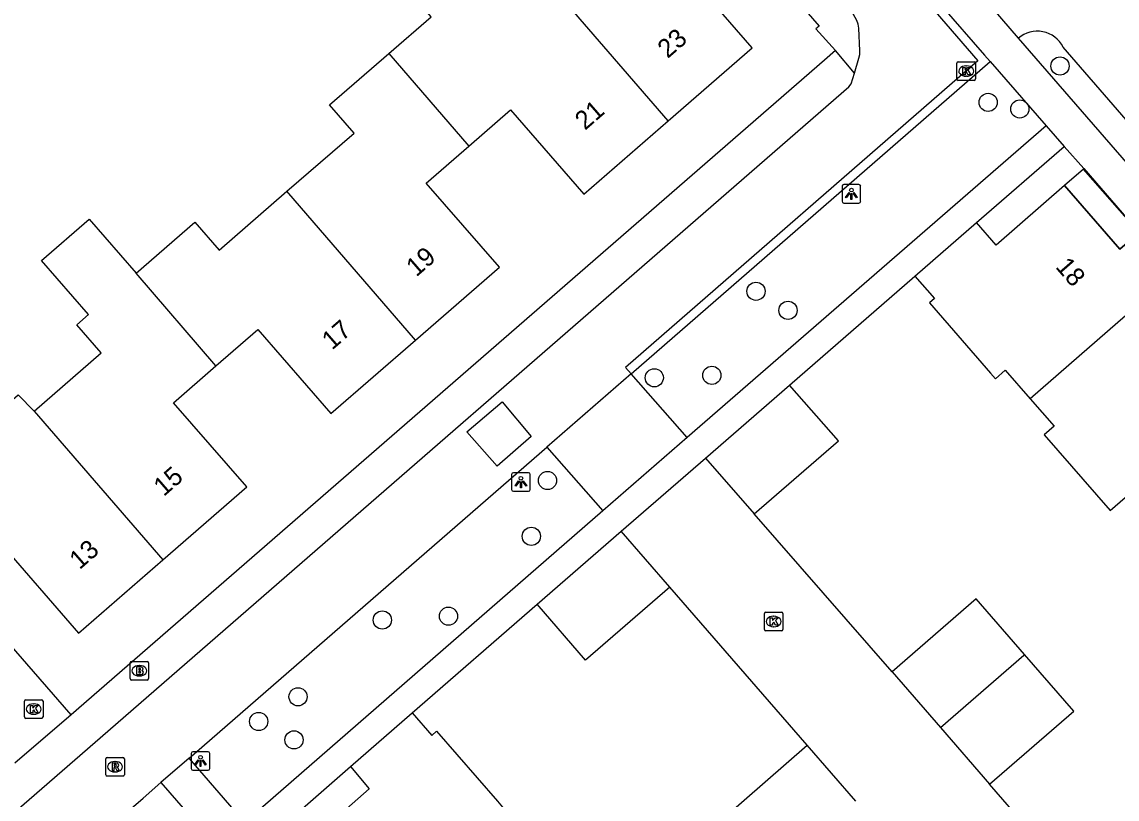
# Model space of a CAD drawing. Extents: x 155888 to 156864, y 383882 to 384671.
# Drawn here: x 156279.9 to 156338.8, y 384195.3 to 384237.1 of the extents above; entities that cross this region are included whole.
import ezdxf

# ---------------------------------------------------------------- set-up
doc = ezdxf.new("R2010")
doc.units = 0
for name, color, linetype in [('IMGEO_Boom', 7, 'Continuous'), ('IMGEO_Brandkraan', 7, 'Continuous'), ('IMGEO_Fietspad_gesloten', 7, 'Continuous'), ('IMGEO_Kolk', 7, 'Continuous'), ('IMGEO_Lichtpunt', 7, 'Continuous'), ('IMGEO_Muur', 7, 'Continuous'), ('IMGEO_Pand', 7, 'Continuous'), ('IMGEO_Pand_nummerreeks', 7, 'Continuous'), ('IMGEO_Pand_overbouw', 7, 'Continuous'), ('IMGEO_Rijbaan_lokaal_gesloten', 7, 'Continuous'), ('IMGEO_Rijbaan_lokaal_open', 7, 'Continuous'), ('IMGEO_Rioolput', 7, 'Continuous'), ('IMGEO_Voetpad_open', 7, 'Continuous')]:
    doc.layers.add(name, color=color, linetype=linetype)

msp = doc.modelspace()

# ---------------------------------------------------------------- linework, layer by layer
at = {"layer": 'IMGEO_Boom'}
for centre in [(156335.691, 384234.728), (156331.826, 384232.771), (156333.53, 384232.42), (156319.34, 384222.609), (156321.063, 384221.583), (156313.87, 384217.956), (156316.967, 384218.087), (156308.129, 384212.429), (156307.261, 384209.427), (156299.244, 384204.922), (156302.801, 384205.128), (156294.714, 384200.793), (156292.594, 384199.464), (156294.493, 384198.473)]:
    msp.add_circle(centre, 0.489, dxfattribs=at)
at = {"layer": 'IMGEO_Brandkraan'}
for p, q in [((156285.677, 384201.769), (156285.677, 384202.621)), ((156285.752, 384202.695), (156286.604, 384202.695)), ((156286.165, 384202.475), (156286.19, 384202.475)), ((156286.678, 384202.621), (156286.678, 384201.769)), ((156286.188, 384201.915), (156286.163, 384201.915)), ((156286.604, 384201.695), (156285.752, 384201.695))]:
    msp.add_line(p, q, dxfattribs=at)
for points in [[(156285.677, 384201.769), (156285.677, 384202.621)], [(156285.752, 384202.695), (156286.604, 384202.695)], [(156286.025, 384202.395), (156286.025, 384201.995), (156286.238, 384201.995)], [(156286.256, 384202.395), (156286.025, 384202.395)], [(156286.678, 384202.621), (156286.678, 384201.769)], [(156286.204, 384202.314), (156286.15, 384202.314), (156286.15, 384202.238)], [(156286.15, 384202.238), (156286.203, 384202.238)], [(156286.212, 384202.162), (156286.15, 384202.162), (156286.15, 384202.081)], [(156286.15, 384202.081), (156286.212, 384202.081)], [(156286.604, 384201.695), (156285.752, 384201.695)]]:
    msp.add_lwpolyline(points, dxfattribs=at)
for centre, radius, start, end in [((156285.754, 384202.619), 0.0765, 91.55205, 178.44795), ((156285.754, 384202.619), 0.0765, 91.55205, 178.44795), ((156286.26, 384202.25), 0.145, 59.4692, 91.53667), ((156286.602, 384202.619), 0.0765, 1.55205, 88.44795), ((156286.602, 384202.619), 0.0765, 1.55205, 88.44795), ((156286.205, 384202.276), 0.0379, 267.82845, 90.93552), ((156286.213, 384202.121), 0.0404, 269.87594, 90.50774), ((156286.244, 384202.246), 0.251, 268.66757, 293.53466), ((156286.285, 384202.297), 0.0922, 285.51372, 58.15012), ((156286.29, 384202.105), 0.105, 301.31148, 78.98903), ((156285.754, 384201.771), 0.0765, 181.55205, 268.44795), ((156285.754, 384201.771), 0.0765, 181.55205, 268.44795), ((156286.602, 384201.771), 0.0765, 271.55205, 358.44795), ((156286.602, 384201.771), 0.0765, 271.55205, 358.44795)]:
    msp.add_arc(centre, radius, start, end, dxfattribs=at)
for centre, major_axis, ratio, start_param, end_param in [((156286.164, 384202.195), (-0.387, 0.002), 0.722429, 4.712389, 7.853982), ((156286.189, 384202.195), (-0.39, 0.002), 0.717154, 1.570796, 4.712389)]:
    msp.add_ellipse(centre, major_axis=major_axis, ratio=ratio, start_param=start_param, end_param=end_param, dxfattribs=at)
at = {"layer": 'IMGEO_Fietspad_gesloten'}
for points in [[(156333.453, 384236.224), (156330.765, 384239.365)], [(156363.796, 384203.508), (156359.945, 384207.962), (156335.855, 384235.751)]]:
    msp.add_lwpolyline(points, dxfattribs=at)
msp.add_arc((156334.468, 384235.043), 1.557, 27.03332, 130.68647, dxfattribs=at)
at = {"layer": 'IMGEO_Kolk'}
for p, q in [((156330.146, 384234.032), (156330.146, 384234.884)), ((156330.221, 384234.958), (156331.073, 384234.958)), ((156331.147, 384234.884), (156331.147, 384234.032)), ((156330.634, 384234.738), (156330.659, 384234.738)), ((156331.073, 384233.958), (156330.221, 384233.958)), ((156330.657, 384234.178), (156330.632, 384234.178)), ((156319.865, 384205.343), (156320.717, 384205.343)), ((156319.79, 384204.417), (156319.79, 384205.269)), ((156320.278, 384205.123), (156320.303, 384205.123)), ((156320.791, 384205.269), (156320.791, 384204.417)), ((156320.717, 384204.343), (156319.865, 384204.343)), ((156320.301, 384204.563), (156320.276, 384204.563)), ((156280.074, 384200.631), (156280.926, 384200.631)), ((156279.999, 384199.705), (156279.999, 384200.557)), ((156280.487, 384200.411), (156280.512, 384200.411)), ((156281, 384200.557), (156281, 384199.705)), ((156280.926, 384199.631), (156280.074, 384199.631)), ((156280.51, 384199.851), (156280.485, 384199.851))]:
    msp.add_line(p, q, dxfattribs=at)
for points in [[(156330.146, 384234.032), (156330.146, 384234.884)], [(156330.221, 384234.958), (156331.073, 384234.958)], [(156331.147, 384234.884), (156331.147, 384234.032)], [(156330.467, 384234.658), (156330.59, 384234.658), (156330.59, 384234.507), (156330.72, 384234.658), (156330.884, 384234.658), (156330.738, 384234.507), (156330.891, 384234.258), (156330.739, 384234.258), (156330.654, 384234.422), (156330.59, 384234.355), (156330.59, 384234.258), (156330.467, 384234.258), (156330.467, 384234.658)], [(156331.073, 384233.958), (156330.221, 384233.958)], [(156319.865, 384205.343), (156320.717, 384205.343)], [(156319.79, 384204.417), (156319.79, 384205.269)], [(156320.111, 384205.043), (156320.234, 384205.043), (156320.234, 384204.892), (156320.364, 384205.043), (156320.528, 384205.043), (156320.382, 384204.892), (156320.535, 384204.643), (156320.383, 384204.643), (156320.298, 384204.807), (156320.234, 384204.74), (156320.234, 384204.643), (156320.111, 384204.643), (156320.111, 384205.043)], [(156320.791, 384205.269), (156320.791, 384204.417)], [(156320.717, 384204.343), (156319.865, 384204.343)], [(156280.074, 384200.631), (156280.926, 384200.631)], [(156279.999, 384199.705), (156279.999, 384200.557)], [(156280.32, 384200.331), (156280.443, 384200.331), (156280.443, 384200.18), (156280.573, 384200.331), (156280.737, 384200.331), (156280.591, 384200.18), (156280.744, 384199.931), (156280.592, 384199.931), (156280.507, 384200.095), (156280.443, 384200.028), (156280.443, 384199.931), (156280.32, 384199.931), (156280.32, 384200.331)], [(156281, 384200.557), (156281, 384199.705)], [(156280.926, 384199.631), (156280.074, 384199.631)]]:
    msp.add_lwpolyline(points, dxfattribs=at)
for centre, start, end in [((156330.223, 384234.882), 91.55205, 178.44795), ((156330.223, 384234.882), 91.55205, 178.44795), ((156331.071, 384234.882), 1.55205, 88.44795), ((156331.071, 384234.882), 1.55205, 88.44795), ((156330.223, 384234.034), 181.55205, 268.44795), ((156330.223, 384234.034), 181.55205, 268.44795), ((156331.071, 384234.034), 271.55205, 358.44795), ((156331.071, 384234.034), 271.55205, 358.44795), ((156319.867, 384205.267), 91.55205, 178.44795), ((156319.867, 384205.267), 91.55205, 178.44795), ((156320.715, 384205.267), 1.55205, 88.44795), ((156320.715, 384205.267), 1.55205, 88.44795), ((156319.867, 384204.419), 181.55205, 268.44795), ((156319.867, 384204.419), 181.55205, 268.44795), ((156320.715, 384204.419), 271.55205, 358.44795), ((156320.715, 384204.419), 271.55205, 358.44795), ((156280.076, 384200.555), 91.55205, 178.44795), ((156280.076, 384200.555), 91.55205, 178.44795), ((156280.924, 384200.555), 1.55205, 88.44795), ((156280.924, 384200.555), 1.55205, 88.44795), ((156280.076, 384199.707), 181.55205, 268.44795), ((156280.076, 384199.707), 181.55205, 268.44795), ((156280.924, 384199.707), 271.55205, 358.44795), ((156280.924, 384199.707), 271.55205, 358.44795)]:
    msp.add_arc(centre, 0.0765, start, end, dxfattribs=at)
for centre, major_axis, ratio, start_param, end_param in [((156330.633, 384234.458), (-0.387, 0.002), 0.722429, 4.712389, 7.853982), ((156330.658, 384234.458), (-0.39, 0.002), 0.717154, 1.570796, 4.712389), ((156320.277, 384204.843), (-0.387, 0.002), 0.722429, 4.712389, 7.853982), ((156320.302, 384204.843), (-0.39, 0.002), 0.717154, 1.570796, 4.712389), ((156280.486, 384200.131), (-0.387, 0.002), 0.722429, 4.712389, 7.853982), ((156280.511, 384200.131), (-0.39, 0.002), 0.717154, 1.570796, 4.712389)]:
    msp.add_ellipse(centre, major_axis=major_axis, ratio=ratio, start_param=start_param, end_param=end_param, dxfattribs=at)
at = {"layer": 'IMGEO_Lichtpunt'}
for p, q in [((156324.876, 384228.352), (156324.068, 384228.352)), ((156324.876, 384228.352), (156324.068, 384228.352)), ((156323.974, 384228.257), (156323.974, 384227.45)), ((156323.974, 384228.257), (156323.974, 384227.45)), ((156324.97, 384227.45), (156324.97, 384228.257)), ((156324.97, 384227.45), (156324.97, 384228.257)), ((156324.068, 384227.356), (156324.876, 384227.356)), ((156324.068, 384227.356), (156324.876, 384227.356)), ((156306.201, 384212.749), (156306.201, 384211.942)), ((156306.201, 384212.749), (156306.201, 384211.942)), ((156307.103, 384212.844), (156306.295, 384212.844)), ((156307.103, 384212.844), (156306.295, 384212.844)), ((156307.197, 384211.942), (156307.197, 384212.749)), ((156307.197, 384211.942), (156307.197, 384212.749)), ((156306.295, 384211.848), (156307.103, 384211.848)), ((156306.295, 384211.848), (156307.103, 384211.848)), ((156288.969, 384197.742), (156288.969, 384196.935)), ((156288.969, 384197.742), (156288.969, 384196.935)), ((156289.871, 384197.837), (156289.063, 384197.837)), ((156289.871, 384197.837), (156289.063, 384197.837)), ((156289.965, 384196.935), (156289.965, 384197.742)), ((156289.965, 384196.935), (156289.965, 384197.742)), ((156289.063, 384196.841), (156289.871, 384196.841)), ((156289.063, 384196.841), (156289.871, 384196.841))]:
    msp.add_line(p, q, dxfattribs=at)
for points in [[(156324.348, 384227.921), (156324.387, 384227.893), (156324.199, 384227.631), (156324.161, 384227.658), (156324.348, 384227.921)], [(156324.45, 384227.873), (156324.497, 384227.873), (156324.497, 384227.551), (156324.45, 384227.551), (156324.45, 384227.873)], [(156324.56, 384227.893), (156324.598, 384227.92), (156324.785, 384227.658), (156324.746, 384227.63), (156324.56, 384227.893)], [(156306.575, 384212.413), (156306.614, 384212.385), (156306.426, 384212.123), (156306.388, 384212.15), (156306.575, 384212.413)], [(156306.787, 384212.385), (156306.825, 384212.412), (156307.012, 384212.15), (156306.973, 384212.122), (156306.787, 384212.385)], [(156306.677, 384212.365), (156306.724, 384212.365), (156306.724, 384212.043), (156306.677, 384212.043), (156306.677, 384212.365)], [(156289.343, 384197.406), (156289.382, 384197.378), (156289.194, 384197.116), (156289.156, 384197.143), (156289.343, 384197.406)], [(156289.445, 384197.358), (156289.492, 384197.358), (156289.492, 384197.036), (156289.445, 384197.036), (156289.445, 384197.358)], [(156289.555, 384197.378), (156289.593, 384197.405), (156289.78, 384197.143), (156289.741, 384197.115), (156289.555, 384197.378)]]:
    msp.add_lwpolyline(points, dxfattribs=at)
for centre in [(156324.473, 384228.055), (156306.7, 384212.547), (156289.468, 384197.54)]:
    msp.add_circle(centre, 0.0994, dxfattribs=at)
for centre, start, end in [((156324.068, 384228.257), 90, 180), ((156324.068, 384228.257), 90, 180), ((156324.876, 384228.257), 0, 90), ((156324.876, 384228.257), 0, 90), ((156324.068, 384227.45), 180, 270), ((156324.068, 384227.45), 180, 270), ((156324.876, 384227.45), 270, 0), ((156324.876, 384227.45), 270, 360), ((156306.295, 384212.749), 90, 180), ((156306.295, 384212.749), 90, 180), ((156307.103, 384212.749), 0, 90), ((156307.103, 384212.749), 0, 90), ((156306.295, 384211.942), 180, 270), ((156306.295, 384211.942), 180, 270), ((156307.103, 384211.942), 270, 0), ((156307.103, 384211.942), 270, 360), ((156289.063, 384197.742), 90, 180), ((156289.063, 384197.742), 90, 180), ((156289.871, 384197.742), 0, 90), ((156289.871, 384197.742), 0, 90), ((156289.063, 384196.935), 180, 270), ((156289.063, 384196.935), 180, 270), ((156289.871, 384196.935), 270, 0), ((156289.871, 384196.935), 270, 360)]:
    msp.add_arc(centre, 0.0946, start, end, dxfattribs=at)
at = {"layer": 'IMGEO_Muur'}
for points in [[(156321.145, 384217.557), (156327.89, 384223.42)], [(156300.85, 384199.926), (156307.581, 384205.768)]]:
    msp.add_lwpolyline(points, dxfattribs=at)
at = {"layer": 'IMGEO_Pand'}
for points in [[(156314.619, 384231.788), (156319.132, 384235.709), (156314.811, 384240.692), (156317.207, 384242.78)], [(156299.601, 384235.408), (156301.869, 384237.381), (156301.28, 384238.058), (156305.386, 384241.63), (156307.289, 384239.443), (156307.705, 384239.805)], [(156314.619, 384231.788), (156307.705, 384239.805)], [(156294.115, 384227.987), (156297.722, 384231.123), (156296.409, 384232.632), (156299.601, 384235.408)], [(156299.601, 384235.408), (156303.892, 384230.413)], [(156303.892, 384230.413), (156306.139, 384232.368), (156310.075, 384227.84), (156314.619, 384231.788)], [(156301.033, 384219.979), (156305.547, 384223.9), (156301.611, 384228.428), (156303.892, 384230.413)], [(156339.942, 384225.767), (156338.91, 384224.87), (156335.933, 384228.294), (156332.25, 384225.097), (156331.203, 384226.305)], [(156286.004, 384223.584), (156289.157, 384226.326), (156290.47, 384224.817), (156294.115, 384227.987)], [(156301.033, 384219.979), (156294.115, 384227.987)], [(156280.518, 384216.162), (156284.124, 384219.298), (156282.811, 384220.807), (156283.441, 384221.355), (156280.917, 384224.258), (156283.48, 384226.486), (156286.004, 384223.584)], [(156327.89, 384223.42), (156331.203, 384226.305)], [(156290.298, 384218.596), (156286.004, 384223.584)], [(156327.89, 384223.42), (156328.939, 384222.213), (156328.675, 384221.983), (156331.955, 384218.209), (156332.218, 384217.907), (156332.745, 384218.367), (156334.094, 384216.817)], [(156341.856, 384223.579), (156334.094, 384216.817)], [(156334.094, 384216.817), (156335.37, 384215.349), (156334.841, 384214.888), (156338.384, 384210.813), (156341.877, 384213.852), (156345.649, 384217.133), (156342.671, 384220.533), (156343.716, 384221.453)], [(156290.298, 384218.596), (156292.543, 384220.553), (156296.479, 384216.025), (156301.033, 384219.979)], [(156287.446, 384208.161), (156291.959, 384212.085), (156288.023, 384216.613), (156290.298, 384218.596)], [(156316.618, 384213.633), (156321.145, 384217.557)], [(156319.24, 384210.63), (156323.772, 384214.559), (156321.145, 384217.557)], [(156272.239, 384211.613), (156275.567, 384214.507), (156276.077, 384213.921), (156279.655, 384217.032), (156280.518, 384216.162)], [(156280.518, 384216.162), (156287.446, 384208.161)], [(156316.618, 384213.633), (156319.24, 384210.63)], [(156307.581, 384205.768), (156312.097, 384209.704)], [(156314.708, 384206.687), (156312.097, 384209.704)], [(156276.178, 384207.086), (156278.574, 384209.202), (156282.907, 384204.214), (156287.446, 384208.161)], [(156314.708, 384206.687), (156310.176, 384202.758), (156307.581, 384205.768)], [(156333.783, 384203.075), (156331.184, 384206.065), (156326.656, 384202.13)], [(156329.26, 384199.135), (156333.74, 384203.038), (156333.783, 384203.075)], [(156331.904, 384196.092), (156336.432, 384200.027), (156333.783, 384203.075)], [(156326.656, 384202.13), (156329.26, 384199.135)], [(156297.529, 384197.043), (156300.85, 384199.926)], [(156300.85, 384199.926), (156301.9, 384198.715), (156302.164, 384198.945), (156305.441, 384195.169), (156305.708, 384194.862), (156305.179, 384194.402), (156306.526, 384192.85)], [(156329.26, 384199.135), (156331.904, 384196.092)], [(156320.165, 384191.267), (156317.573, 384194.249), (156322.101, 384198.184)], [(156324.711, 384195.181), (156322.101, 384198.184)], [(156297.529, 384197.043), (156298.545, 384195.838), (156294.873, 384192.617), (156297.841, 384189.175), (156296.822, 384188.298)]]:
    msp.add_lwpolyline(points, dxfattribs=at)
at = {"layer": 'IMGEO_Pand_overbouw'}
msp.add_lwpolyline([(156339.942, 384225.767), (156336.955, 384229.181), (156335.933, 384228.294), (156338.91, 384224.87)], close=True, dxfattribs=at)
at = {"layer": 'IMGEO_Rijbaan_lokaal_gesloten'}
for points in [[(156326.065, 384241.018), (156328.971, 384237.669), (156331.278, 384235.009), (156312.322, 384218.504), (156312.626, 384218.159)], [(156324.635, 384234.343), (156324.879, 384235.149), (156324.922, 384235.346), (156324.924, 384235.545), (156324.868, 384236.767), (156324.839, 384236.98), (156324.76, 384237.181), (156323.695, 384239.126)], [(156239.684, 384160.03), (156283.805, 384198.344), (156324.33, 384233.603), (156324.464, 384233.777), (156324.635, 384234.343)], [(156312.626, 384218.159), (156308.096, 384214.226)], [(156288.85, 384197.49), (156308.096, 384214.226)], [(156288.85, 384197.49), (156287.336, 384196.173)], [(156282.391, 384191.885), (156283.307, 384192.681), (156286.385, 384195.346), (156287.336, 384196.173)]]:
    msp.add_lwpolyline(points, dxfattribs=at)
at = {"layer": 'IMGEO_Rijbaan_lokaal_open'}
for points in [[(156326.424, 384241.306), (156329.317, 384237.972), (156331.622, 384235.315), (156331.928, 384234.965)], [(156312.626, 384218.159), (156331.928, 384234.965)], [(156315.64, 384214.734), (156312.626, 384218.159)], [(156303.787, 384215.046), (156305.684, 384216.666), (156307.257, 384214.801), (156305.425, 384213.202), (156303.787, 384215.046)], [(156308.096, 384214.226), (156311.102, 384210.8)], [(156315.64, 384214.734), (156311.102, 384210.8)], [(156312.097, 384209.704), (156316.618, 384213.633)], [(156326.656, 384202.13), (156319.24, 384210.63)], [(156322.101, 384198.184), (156314.708, 384206.687)], [(156337.983, 384189.1), (156331.904, 384196.092)]]:
    msp.add_lwpolyline(points, dxfattribs=at)
at = {"layer": 'IMGEO_Rioolput'}
for p, q in [((156284.37, 384196.602), (156284.37, 384197.454)), ((156284.445, 384197.528), (156285.297, 384197.528)), ((156284.858, 384197.308), (156284.883, 384197.308)), ((156285.371, 384197.454), (156285.371, 384196.602)), ((156285.297, 384196.528), (156284.445, 384196.528)), ((156284.881, 384196.748), (156284.856, 384196.748))]:
    msp.add_line(p, q, dxfattribs=at)
for points in [[(156284.37, 384196.602), (156284.37, 384197.454)], [(156284.445, 384197.528), (156285.297, 384197.528)], [(156284.959, 384197.226), (156284.707, 384197.228), (156284.707, 384196.828)], [(156284.885, 384197.147), (156284.831, 384197.147), (156284.831, 384197.066)], [(156285.371, 384197.454), (156285.371, 384196.602)], [(156285.297, 384196.528), (156284.445, 384196.528)], [(156284.707, 384196.828), (156284.831, 384196.828), (156284.831, 384196.99), (156284.842, 384196.99)], [(156284.831, 384197.066), (156284.883, 384197.066)], [(156284.889, 384196.961), (156284.96, 384196.828), (156285.1, 384196.828), (156285.035, 384196.954)]]:
    msp.add_lwpolyline(points, dxfattribs=at)
for centre, radius, start, end in [((156284.447, 384197.452), 0.0765, 91.55205, 178.44795), ((156284.447, 384197.452), 0.0765, 91.55205, 178.44795), ((156284.891, 384197.051), 0.0964, 77.00612, 93.18647), ((156284.905, 384197.108), 0.0378, 276.66336, 79.67722), ((156284.958, 384197.116), 0.109, 350.36119, 89.41601), ((156284.956, 384197.116), 0.112, 277.58423, 350.98172), ((156285.295, 384197.452), 0.0765, 1.55205, 88.44795), ((156285.295, 384197.452), 0.0765, 1.55205, 88.44795), ((156284.447, 384196.604), 0.0765, 181.55205, 268.44795), ((156284.447, 384196.604), 0.0765, 181.55205, 268.44795), ((156284.841, 384196.937), 0.0533, 26.02933, 88.69889), ((156284.867, 384197.255), 0.19, 274.7715, 282.96867), ((156284.94, 384196.901), 0.108, 29.51342, 73.79051), ((156285.295, 384196.604), 0.0765, 271.55205, 358.44795), ((156285.295, 384196.604), 0.0765, 271.55205, 358.44795)]:
    msp.add_arc(centre, radius, start, end, dxfattribs=at)
for centre, major_axis, ratio, start_param, end_param in [((156284.857, 384197.028), (-0.387, 0.002), 0.722429, 4.712389, 7.853982), ((156284.882, 384197.028), (-0.39, 0.002), 0.717154, 1.570796, 4.712389)]:
    msp.add_ellipse(centre, major_axis=major_axis, ratio=ratio, start_param=start_param, end_param=end_param, dxfattribs=at)
at = {"layer": 'IMGEO_Voetpad_open'}
for points in [[(156317.207, 384242.78), (156317.444, 384242.973), (156322.738, 384236.866), (156322.559, 384236.725), (156323.619, 384235.555)], [(156362.704, 384202.562), (156358.843, 384206.998), (156333.453, 384236.224)], [(156323.619, 384235.555), (156323.027, 384235.041), (156282.504, 384199.826)], [(156324.635, 384234.343), (156323.619, 384235.555)], [(156331.928, 384234.965), (156334.947, 384231.513)], [(156334.947, 384231.513), (156315.64, 384214.734)], [(156334.947, 384231.513), (156335.922, 384230.405)], [(156331.203, 384226.305), (156335.922, 384230.405)], [(156335.922, 384230.405), (156336.978, 384229.208), (156339.942, 384225.767)], [(156321.145, 384217.557), (156327.89, 384223.42)], [(156311.102, 384210.8), (156291.852, 384194.029), (156288.85, 384197.49)], [(156282.504, 384199.826), (156276.178, 384207.086)], [(156300.85, 384199.926), (156307.581, 384205.768)], [(156282.504, 384199.826), (156279.482, 384197.222)], [(156292.801, 384192.905), (156297.529, 384197.043)], [(156287.336, 384196.173), (156290.338, 384192.715), (156285.394, 384188.423), (156282.391, 384191.885)]]:
    msp.add_lwpolyline(points, dxfattribs=at)

# ---------------------------------------------------------------- texts
at = {"layer": 'IMGEO_Pand_nummerreeks'}
for s, rotation, p in [('23', 40.98511, (156314.591, 384235.103)), ('21', 40.98367, (156310.147, 384231.242)), ('19', 40.97231, (156301.072, 384223.352)), ('18', 311.04059, (156335.407, 384223.902)), ('17', 40.97231, (156296.538, 384219.414)), ('15', 41.00659, (156287.487, 384211.537)), ('13', 41.00659, (156282.961, 384207.601))]:
    msp.add_text(s, height=1, rotation=rotation, dxfattribs=at).set_placement(p)

doc.saveas('drawing.dxf')
